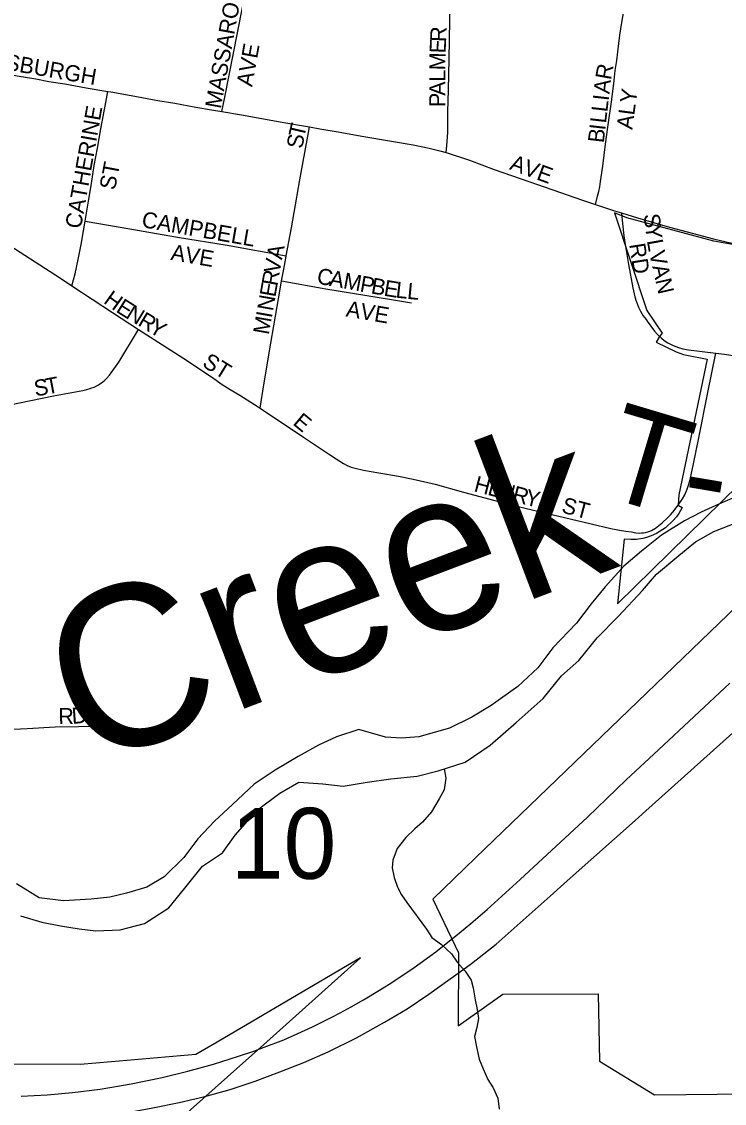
# Model space of a CAD drawing. Extents: x 1985906 to 2360102, y 891258 to 1222054.
# Drawn here: x 2126472 to 2128661, y 1016563 to 1019933 of the extents above; entities that cross this region are included whole.
import ezdxf

# ---------------------------------------------------------------- set-up
doc = ezdxf.new("R2010")
doc.units = 0
for name, color, linetype in [('GM_X_City_Street', 7, 'Continuous'), ('GM_X_City_Street_Text', 7, 'Continuous'), ('GM_X_Corporation', 7, 'Continuous'), ('GM_X_County_Road', 7, 'Continuous'), ('GM_X_Minor_River', 7, 'Continuous'), ('GM_X_Minor_River_Text', 7, 'Continuous'), ('GM_X_Section_Text', 7, 'Continuous'), ('GM_X_Township_Road', 7, 'Continuous'), ('GM_X_Township_Road_Text', 7, 'Continuous'), ('GM_X_US_Route', 7, 'Continuous')]:
    doc.layers.add(name, color=color, linetype=linetype)

msp = doc.modelspace()

# ---------------------------------------------------------------- linework, layer by layer
at = {"layer": 'GM_X_City_Street'}
for points in [[(2127095.8, 1019653.2), (2127103.5, 1019692.7), (2127172, 1020042.2), (2127178.8, 1020106.2), (2127180.3, 1020252.1), (2127178.4, 1020365.6), (2127176.6, 1020397.9), (2127174.9, 1020428.1)], [(2128258.9, 1019364.2), (2128265.8, 1019389.2), (2128269.9, 1019404.1), (2128272.4, 1019418.9), (2128275, 1019435.3), (2128281.7, 1019483.4), (2128290.4, 1019552.1), (2128297.9, 1019604.9), (2128310, 1019690.3), (2128317.1, 1019749.5), (2128321, 1019781.1), (2128325.3, 1019812.6), (2128328.9, 1019838.9), (2128335.6, 1019891.1), (2128341.7, 1019931.1), (2128352, 1019989.4), (2128359.7, 1020047.8), (2128361.9, 1020079.6), (2128362.7, 1020108.3)], [(2127794.7, 1019525.7), (2127796.3, 1019547.6), (2127799.2, 1019587.8), (2127799.9, 1019652.8), (2127801.2, 1019720.5), (2127803.1, 1019817.4), (2127806.9, 1019997.4), (2127807.3, 1020027.8), (2127808.1, 1020058.7), (2127809.1, 1020102.4)], [(2126257.6, 1019799.1), (2126279.6, 1019795.4), (2126366.3, 1019780.8), (2126457.9, 1019765), (2126516.1, 1019754.9), (2126557.2, 1019747.3), (2126606.5, 1019739.1), (2126672.9, 1019727.1), (2126740.9, 1019715.8)], [(2126670.1, 1019311.5), (2126680.4, 1019373.7), (2126689.3, 1019428.9), (2126698.3, 1019485.6), (2126707.9, 1019539.4), (2126718.3, 1019599.8), (2126734.3, 1019681.9), (2126740.9, 1019715.8)], [(2126740.9, 1019715.8), (2126749.4, 1019714.4), (2126813.2, 1019703), (2126896, 1019687.8), (2126949.2, 1019678.9), (2127014.9, 1019666.9), (2127063.6, 1019658.7), (2127095.8, 1019653.2)], [(2127095.8, 1019653.2), (2127156.5, 1019642.6), (2127208.5, 1019633.5), (2127271, 1019622.5), (2127337.7, 1019610.8), (2127368.6, 1019605.3)], [(2127296.4, 1019204.1), (2127312.1, 1019290.6), (2127320.7, 1019338.8), (2127338.9, 1019440.7), (2127347.1, 1019486.5), (2127363, 1019576.1), (2127368.6, 1019605.3)], [(2127368.6, 1019605.3), (2127400.3, 1019599.8), (2127458.1, 1019589.7), (2127531.4, 1019576.4), (2127624.4, 1019560.6), (2127691.4, 1019549.1), (2127741.3, 1019539.7), (2127774.8, 1019531.4), (2127794.7, 1019525.7)], [(2127794.7, 1019525.7), (2127866.5, 1019501.7), (2127944, 1019473.1), (2128051.7, 1019435.3), (2128222.4, 1019376.4), (2128258.9, 1019364.2)], [(2126201.4, 1019371.3), (2126206.4, 1019371.8), (2126212.2, 1019371.9), (2126217.6, 1019371.4), (2126224.2, 1019369.9), (2126228.7, 1019368.3), (2126233.3, 1019366), (2126238.2, 1019363.1), (2126279.8, 1019337), (2126401.8, 1019257.2), (2126593, 1019134.1), (2126628.9, 1019110.3)], [(2128258.9, 1019364.2), (2128318.5, 1019344.2), (2128340.3, 1019337.4)], [(2128340.3, 1019337.4), (2128390, 1019322), (2128489.5, 1019292.8)], [(2128340.3, 1019337.4), (2128343.5, 1019305), (2128347.4, 1019266.2), (2128352.5, 1019233), (2128362.1, 1019176.9), (2128375.4, 1019104.5), (2128382.3, 1019075.6), (2128386, 1019062.8)], [(2126628.9, 1019110.3), (2126638.8, 1019148.2), (2126648.5, 1019192), (2126657.8, 1019238.6), (2126665.1, 1019282), (2126670.1, 1019311.5)], [(2126670.1, 1019311.5), (2126785.3, 1019291.6), (2126957.7, 1019261.8), (2127111.8, 1019236.7), (2127296.4, 1019204.1)], [(2127281.3, 1019126.4), (2127288.4, 1019162.6), (2127295.1, 1019196.6), (2127296.4, 1019204.1)], [(2126628.9, 1019110.3), (2126755.2, 1019026.8), (2126836.3, 1018974.5)], [(2127215.4, 1018729.2), (2127226.5, 1018802), (2127248.3, 1018931.5), (2127257.5, 1018985.5), (2127267.7, 1019046), (2127276.8, 1019099.8), (2127281.3, 1019126.4)], [(2127281.3, 1019126.4), (2127419.1, 1019101.1), (2127630.4, 1019066.5), (2127686.2, 1019057.8)], [(2128386, 1019062.8), (2128386.7, 1019060.3), (2128393.6, 1019043.4), (2128399.7, 1019031.4), (2128408.1, 1019017.3), (2128416.6, 1019005.5)], [(2126340, 1018720.3), (2126363.5, 1018725), (2126571.2, 1018767.2), (2126662.3, 1018784.6), (2126674.6, 1018787.3), (2126682.7, 1018789.9), (2126690.7, 1018792.5), (2126697.6, 1018795.1), (2126711.5, 1018802.2), (2126724.6, 1018811), (2126729.8, 1018815.1), (2126736.1, 1018821.3), (2126745.4, 1018832.5), (2126774.7, 1018872.9), (2126836.3, 1018974.5)], [(2126836.3, 1018974.5), (2126974.3, 1018885.8), (2127063.2, 1018827.1), (2127096.4, 1018803.4), (2127121.4, 1018786.9), (2127151.8, 1018770), (2127208.9, 1018733.7), (2127215.4, 1018729.2)], [(2127215.4, 1018729.2), (2127349.4, 1018638.4), (2127430.4, 1018584.4), (2127451.2, 1018571.5), (2127474.4, 1018557.1), (2127486.2, 1018550.8), (2127498.6, 1018545.8), (2127510.7, 1018541.9), (2127536.8, 1018536.5), (2127584.1, 1018528.2), (2127645.7, 1018517.3), (2127691.1, 1018507.7), (2127760.2, 1018492.5), (2127847.8, 1018467.5), (2127992.9, 1018429.3), (2128062, 1018412.7), (2128307.4, 1018353.9), (2128334.4, 1018348.7), (2128353.6, 1018346.1), (2128371.5, 1018343.7)], [(2125502.4, 1017856.4), (2125513.3, 1017856), (2125545.4, 1017853.3), (2125569.6, 1017849.9), (2125590.3, 1017847), (2125622.6, 1017839.3), (2125653.7, 1017827.1), (2125796.4, 1017747.1), (2125812.5, 1017740.4), (2125825.9, 1017735.4), (2125841.4, 1017731.4), (2125858.2, 1017728.5), (2125877.9, 1017727.2), (2125916.7, 1017726.6), (2125994.3, 1017725.9), (2126231.3, 1017724.9), (2126370.9, 1017726.4), (2126427.3, 1017728), (2126489.1, 1017730.9), (2126576.6, 1017736), (2126649.3, 1017737.8), (2126688.9, 1017738.2)]]:
    msp.add_lwpolyline(points, dxfattribs=at)
at = {"layer": 'GM_X_Corporation'}
for points in [[(2128902.1, 1019200.5), (2128628, 1019249.4), (2128356.7, 1019322.4), (2128318.7, 1019337.8), (2128419, 1019033.6), (2128466.8, 1018963), (2128458.6, 1018952.9), (2128448.7, 1018934.8), (2128510.6, 1018905.1), (2128533.6, 1018895.9), (2128606.9, 1018881.5), (2128519.2, 1018459), (2128516.7, 1018427.1), (2128529.1, 1018419.8), (2128518.4, 1018401.1), (2128511.3, 1018391.1), (2128501.6, 1018379.3), (2128477.1, 1018356.4), (2128449.1, 1018338.6), (2128432.6, 1018331.2), (2128418.6, 1018326.4), (2128407.1, 1018323.5), (2128386.6, 1018320.4), (2128368.9, 1018319.8), (2128348.4, 1018321.5), (2128328.1, 1018119.4), (2129032.1, 1018810.1)], [(2128981.1, 1018383.6), (2127885.1, 1017328), (2127752.2, 1017200), (2127832.4, 1017032.6), (2127832, 1016804.6), (2127970.7, 1016903.5), (2128267.9, 1016904.2), (2128271.5, 1016694.8), (2128443.4, 1016589.6), (2128735.3, 1016593.6)], [(2126873.4, 1016431.9), (2127112.8, 1016645.8), (2127235.7, 1016755.6), (2127527.7, 1017016.5), (2127080.6, 1016754.3), (2127014.3, 1016715.8), (2126751.6, 1016693), (2126654.1, 1016684.5), (2126198.3, 1016687.1), (2125935.6, 1016728.4), (2125840.3, 1016750.3), (2125404.1, 1016850.3), (2125373.8, 1016869.8), (2125348.9, 1016861.2), (2125308, 1016831.7), (2125267, 1016802.3), (2125181.9, 1016730.4), (2125440.7, 1016635.2), (2125546.7, 1016604), (2125629.3, 1016582.2), (2125429.6, 1016087.8)]]:
    msp.add_lwpolyline(points, dxfattribs=at)
at = {"layer": 'GM_X_County_Road'}
msp.add_lwpolyline([(2128489.5, 1019292.8), (2128545.3, 1019278.1), (2128626.9, 1019256.7), (2128763.2, 1019224.3), (2128911, 1019188.9)], dxfattribs=at)
at = {"layer": 'GM_X_Minor_River'}
for points in [[(2128707.5, 1018457.8), (2128645.7, 1018431.3), (2128587.9, 1018404.8), (2128536.1, 1018378.4), (2128464.4, 1018333.8), (2128402.7, 1018283.3), (2128347.1, 1018236.8), (2128289.5, 1018172.3), (2128245.9, 1018119.9), (2128200.3, 1018059.5), (2128126.8, 1017982.9), (2128079.3, 1017920.4), (2128017.7, 1017861.9), (2127934.1, 1017803.2), (2127874.4, 1017766.7), (2127804.6, 1017732.2), (2127708.8, 1017705.4), (2127654.8, 1017701), (2127604.8, 1017704.6), (2127522.7, 1017728), (2127452.8, 1017705.5), (2127397, 1017679), (2127333.3, 1017644.5), (2127261.6, 1017601.9), (2127195.9, 1017557.4), (2127128.3, 1017494.8), (2127072.7, 1017442.3), (2127021.1, 1017387.9), (2126977.5, 1017329.5), (2126915.9, 1017268.9), (2126862.1, 1017236.5), (2126798.3, 1017218), (2126746.4, 1017205.6), (2126688.4, 1017199.1)], [(2126779.1, 1017103.7), (2126854.9, 1017124.3), (2126930.6, 1017172.9), (2126980.1, 1017233.4), (2127035.7, 1017301.9), (2127097.4, 1017344.4), (2127137, 1017398.7), (2127206.4, 1017477.4), (2127276.1, 1017529.9), (2127335.8, 1017564.4), (2127409.8, 1017559), (2127473.9, 1017551.5), (2127547.8, 1017564), (2127621.7, 1017574.6), (2127703.6, 1017583.2), (2127769.5, 1017599.7), (2127853.3, 1017626.4), (2127931, 1017679), (2128012.4, 1017749.8), (2128095.9, 1017824.5), (2128153.4, 1017895), (2128207.1, 1017943.4), (2128264.6, 1018014), (2128330.1, 1018080.5), (2128405.6, 1018161.2), (2128449.2, 1018211.6), (2128518.8, 1018270.2), (2128570.5, 1018312.6), (2128628.3, 1018345.1), (2128686.1, 1018367.5)], [(2127788.1, 1017605.7), (2127793.2, 1017576.3), (2127787.7, 1017540.2), (2127772, 1017511.9), (2127748.4, 1017471.5), (2127720.7, 1017439), (2127696.9, 1017418.6), (2127669.1, 1017392.2), (2127641.4, 1017357.7), (2127627.8, 1017321.4), (2127626.1, 1017297.3), (2127632.6, 1017267.4), (2127643, 1017237.4), (2127655.3, 1017213.5), (2127671.7, 1017189.7), (2127733, 1017106.2), (2127749.4, 1017080.4), (2127779.9, 1017058.7), (2127810.4, 1017029), (2127828.8, 1017003.2), (2127853.2, 1016975.5), (2127871.7, 1016947.6), (2127878, 1016923.6), (2127884.5, 1016885.6), (2127890.9, 1016855.6), (2127895.3, 1016827.6), (2127889.7, 1016799.4), (2127882, 1016771.3), (2127888.4, 1016739.3), (2127896.9, 1016701.3), (2127909.4, 1016671.3), (2127923.9, 1016637.4), (2127940.3, 1016611.6), (2127954.8, 1016579.7), (2127959.2, 1016545.7)], [(2126688.4, 1017199.1), (2126602.5, 1017194.5), (2126526.4, 1017203.9), (2126456.1, 1017247.4)], [(2126468.8, 1017147.4), (2126534.9, 1017127.9), (2126593, 1017116.3), (2126651.1, 1017106.8), (2126703.1, 1017101.1), (2126779.1, 1017103.7)]]:
    msp.add_lwpolyline(points, dxfattribs=at)
at = {"layer": 'GM_X_Township_Road'}
for points in [[(2128416.6, 1019005.5), (2128420.2, 1019000.4), (2128443.2, 1018969.4), (2128452.6, 1018958.9), (2128464.7, 1018946.8), (2128473.6, 1018940.1), (2128484.9, 1018933.1), (2128495.3, 1018927.7), (2128501.4, 1018924.6), (2128517.3, 1018918.2), (2128531.2, 1018914.4), (2128548.5, 1018910.5), (2128633.8, 1018900.1)], [(2128371.5, 1018343.7), (2128380, 1018342), (2128384.6, 1018341.3), (2128395.2, 1018340.3), (2128402.8, 1018340.5), (2128408.6, 1018340.9), (2128414.6, 1018342.1), (2128421.8, 1018344), (2128433.9, 1018348.1), (2128446.5, 1018355.6), (2128466.6, 1018371.8), (2128483.2, 1018387.7), (2128492.5, 1018397), (2128499.7, 1018404.9), (2128516.7, 1018427.1), (2128529.8, 1018446.5), (2128537.2, 1018459.6), (2128545, 1018477), (2128550, 1018492.2), (2128553.8, 1018507.1), (2128564.3, 1018555.7), (2128581.6, 1018636.3), (2128609.1, 1018778.5), (2128633.8, 1018900.1)], [(2128633.8, 1018900.1), (2128660.7, 1018897.3), (2128766.9, 1018881.2), (2128790.6, 1018876.8)]]:
    msp.add_lwpolyline(points, dxfattribs=at)
at = {"layer": 'GM_X_US_Route'}
for points in [[(2126470.9, 1016585.4), (2126551.5, 1016590.4), (2126630.4, 1016597.3), (2126716.3, 1016607.9), (2126813.5, 1016624.4), (2126910.1, 1016644.2), (2126989.9, 1016663.3), (2127069.1, 1016685.3), (2127147.3, 1016710.4), (2127195.6, 1016726.4), (2127227.6, 1016738.6), (2127288.9, 1016761.7), (2127332.2, 1016780.8), (2127378.4, 1016802.1), (2127436.1, 1016831.1), (2127464.4, 1016845.8), (2127498.7, 1016864.1), (2127537, 1016886), (2127587.1, 1016915.7), (2127625, 1016940.4), (2127694.2, 1016986.8), (2127761.6, 1017035.8), (2127836, 1017094.4), (2127870.8, 1017123.5), (2127922.1, 1017167.9), (2128025, 1017261), (2128234, 1017455.2), (2128354.8, 1017571.6), (2128455.2, 1017664.8), (2128677.5, 1017872.7)], [(2128406, 1017465.8), (2128807.2, 1017825.9)], [(2127834.7, 1016971.6), (2127872.9, 1016998.9), (2127949.8, 1017059.7), (2128117.7, 1017209), (2128171.3, 1017256.5), (2128391.7, 1017453.1), (2128406, 1017465.8)], [(2127042.6, 1016584.6), (2127121.7, 1016606.8), (2127199.6, 1016632.7), (2127276, 1016661.5), (2127350.9, 1016690.7), (2127426.9, 1016724.2), (2127515.4, 1016768.1), (2127601.7, 1016816.5), (2127673, 1016857.7), (2127739.9, 1016903.8), (2127807.1, 1016951.4), (2127834.7, 1016971.6)], [(2125932.9, 1016569.4), (2125939.2, 1016567.8), (2126019.6, 1016550.3), (2126100.3, 1016536.2), (2126181.6, 1016525.1), (2126263.2, 1016517.4), (2126292.9, 1016515.5), (2126361.3, 1016511.3), (2126443.7, 1016508.8), (2126524.4, 1016510.4), (2126606.3, 1016514.5), (2126704.4, 1016522.8), (2126802, 1016535.2), (2126881.1, 1016549.3), (2126962.4, 1016565.9), (2127011.6, 1016577.4), (2127042.6, 1016584.6)]]:
    msp.add_lwpolyline(points, dxfattribs=at)

# ---------------------------------------------------------------- texts
at = {"layer": 'GM_X_City_Street_Text'}
for s, rotation, p in [('MASSARO', 79.6943, (2127092.1, 1019660.2)), ('R', 87.4007, (2127793.9, 1019869.1)), ('E', 87.5128, (2127792.3, 1019833.9)), ('PITTSBURGH', 350.2161, (2126275.9, 1019808.6)), ('AVE', 79.8732, (2127189.9, 1019728.6)), ('M', 89.1439, (2127791.6, 1019781.5)), ('L', 89.9727, (2127791.5, 1019746.5)), ('R', 79.6973, (2128307.3, 1019749.7)), ('A', 89.9703, (2127791.5, 1019702.5)), ('A', 83.4854, (2128302.5, 1019706.9)), ('P', 89.9727, (2127791.5, 1019667.3)), ('I', 83.474, (2128300, 1019685)), ('ALY', 82.4025, (2128374, 1019595.6)), ('CATHERINE', 79.9512, (2126656.4, 1019286)), ('L', 83.4833, (2128296, 1019650)), ('L', 83.4857, (2128292, 1019615.1)), ('T', 76.8518, (2127351.6, 1019569.7)), ('I', 83.4823, (2128289.5, 1019593.2)), ('S', 82.3277, (2127347.1, 1019536)), ('B', 83.4774, (2128285, 1019553.8)), ('AVE', 339.6767, (2127989, 1019473.8)), ('ST', 79.3721, (2126763, 1019406.8)), ('CAMPBELL', 350.0361, (2126843.4, 1019293.8)), ('S', 277.2318, (2128408.8, 1019332.3)), ('Y', 277.2343, (2128413.2, 1019297.4)), ('AVE', 350.2153, (2126934.3, 1019191.4)), ('A', 78.3793, (2127282.7, 1019189.8)), ('RD', 278.9785, (2128364, 1019239.6)), ('L', 280.0718, (2128419.1, 1019251)), ('V', 80.0347, (2127275.1, 1019146.8)), ('V', 282.8886, (2128425.8, 1019213.8)), ('C', 349.7191, (2127389, 1019117.8)), ('A', 282.8275, (2128435.6, 1019170.9)), ('R', 80.0337, (2127268.3, 1019107.8)), ('A', 349.7338, (2127428, 1019110.7)), ('M', 349.7171, (2127471.3, 1019102.9)), ('P', 349.7327, (2127523.2, 1019093.4)), ('B', 349.7191, (2127557.8, 1019087.2)), ('N', 282.8313, (2128445.4, 1019128)), ('H', 324.1574, (2126724.3, 1019058.7)), ('E', 80.0324, (2127262.2, 1019073.2)), ('E', 350.7603, (2127597.8, 1019079.9)), ('L', 353.8098, (2127635.4, 1019073.9)), ('L', 354.5167, (2127671.1, 1019070)), ('E', 327.9266, (2126762.9, 1019031)), ('N', 80.0411, (2127254.6, 1019029.8)), ('N', 328.7593, (2126793.4, 1019011.8)), ('R', 328.778, (2126831, 1018989)), ('I', 80.0275, (2127250.8, 1019008.1)), ('AVE', 350.219, (2127479.9, 1019015.4)), ('Y', 328.787, (2126864.9, 1018968.5)), ('M', 80.0421, (2127241.6, 1018956.1)), ('ST', 328.3817, (2127031.5, 1018861.3)), ('T', 10.7698, (2126551.1, 1018771.6)), ('S', 9.0401, (2126514.7, 1018765.8)), ('E', 320.1908, (2127314.1, 1018680.1)), ('H', 345.3966, (2127878.1, 1018470.8)), ('E', 345.374, (2127920.7, 1018459.7)), ('N', 345.395, (2127954.7, 1018450.8)), ('R', 345.3924, (2127997.3, 1018439.7)), ('Y', 346.4793, (2128036.6, 1018429.5)), ('ST', 345.069, (2128150.9, 1018404.8)), ('R', 0.6922, (2126586.7, 1017744.9)), ('D', 4.2033, (2126629.6, 1017745.6))]:
    msp.add_text(s, height=50, rotation=rotation, dxfattribs=at).set_placement(p)
at = {"layer": 'GM_X_Minor_River_Text'}
msp.add_text('Creek', height=500.14, rotation=20.7639, dxfattribs=at).set_placement((2126670.6, 1017605.4))
at = {"layer": 'GM_X_Section_Text'}
msp.add_text('10', height=221, rotation=0, dxfattribs=at).set_placement((2127123.3, 1017263))
at = {"layer": 'GM_X_Township_Road_Text'}
for s, rotation, p in [('T', 343.304, (2128262.7, 1018461.8)), ('-', 350.3846, (2128517, 1018388.1))]:
    msp.add_text(s, height=300, rotation=rotation, dxfattribs=at).set_placement(p)

doc.saveas('drawing.dxf')
